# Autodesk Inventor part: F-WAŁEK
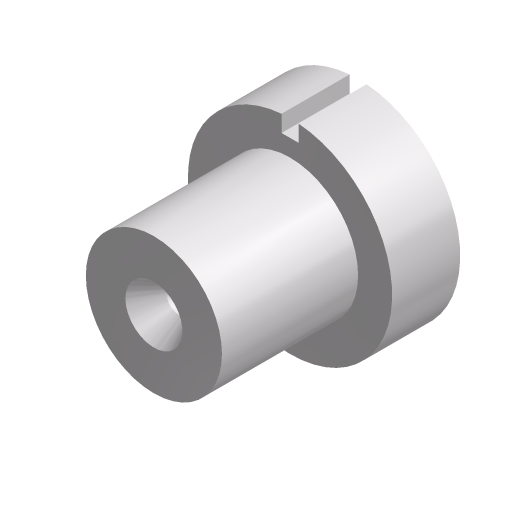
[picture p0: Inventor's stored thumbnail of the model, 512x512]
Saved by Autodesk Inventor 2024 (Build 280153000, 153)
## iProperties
Company: ATC
Shininess: 20.0
Length Units: 11269
Angle Units: 11279
Time Units: 11290
Mass Units: 11283
Length Display Precision: 3
Angle Display Precision: 2
Created: 2023-03
Part Number: F-WAŁEK
Document SubType Name: Modeling
Designer: Andrzej Jaskulski
Material: Kurs-AJ
Density: 1 g/cm^3
Appearance: Kurs-AJ
Checked By: A.J.
Engr Approved By: Andrzej Jaskulski
Mfg Approved By: Andrzej Jaskulski
Authority: A.J.
Density: 0.0
Volumn: 0.0
Area: 0.0
PropertySet Name: Model Information
Control State: 0
Master: False
Checked Out: False
Title: A.J.: Kurs R2024-MEP
Author: Andrzej Jaskulski
Revision Number: 1/24
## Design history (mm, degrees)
node "Czop środkowy" dims "d1" = 4, "d2" = 0
node "Płaszczyzna konstrukcyjna6"
workaxis "Work Axis1"
node "Czop końcowy" dims "d5" = 8, "d6" = 0
node "Nakiełek" dims "d9" = 1.6, "d10" = 3.35, "d11" = 2, "d12" = 60 deg, "d13" = 4.3, "d14" = 120 deg, "d30" = 6
sketch "Szkic5"
  geometry: L1 (0, -0.8)-(0, 4.8) reference; L2 (-6, 4)-(6, 4) reference; L3 (-6, 0)-(6, 0) reference; L4 (-0.5, 4)-(0.5, 4); L5 (0.5, 4)-(0.5, 0); L6 (0.5, 0)-(-0.5, 0); L7 (-0.5, 0)-(-0.5, 4); 2 further points
  constraints: 8 end point, 4 midpoint, 2 parallel, 1 horizontal, 1 perpendicular
  dimensions: "d37" = 1 distance between parallel lines of L5 L7
extrude "Wyciągnięcie proste4" cut sketch "Szkic5" distance "d38" = 1; taper "d39" = 0 deg
node "Bryła1"
node "Korpusy bryłowe"
node "Korpusy powierzchniowe"
sketch "Sketch1"
  geometry: C1 r 6 at (0, 0)
  constraints: 1 centre point, 1 other
  dimensions: "d3" = 12 diameter of C1
sketch "Sketch2"
  geometry: C1 r 6 at (0, 0); C2 r 4 at (0, 0)
  constraints: 2 centre point, 1 coincident
  dimensions: "d4" = 8 diameter of C2
sketch "Sketch3"
  geometry: C1 r 4 at (0, 0) reference; 1 further point
  constraints: 1 coincident
other parameters: "d24" = 45 (derived), "dlugosc" = 16 [user parameter]
